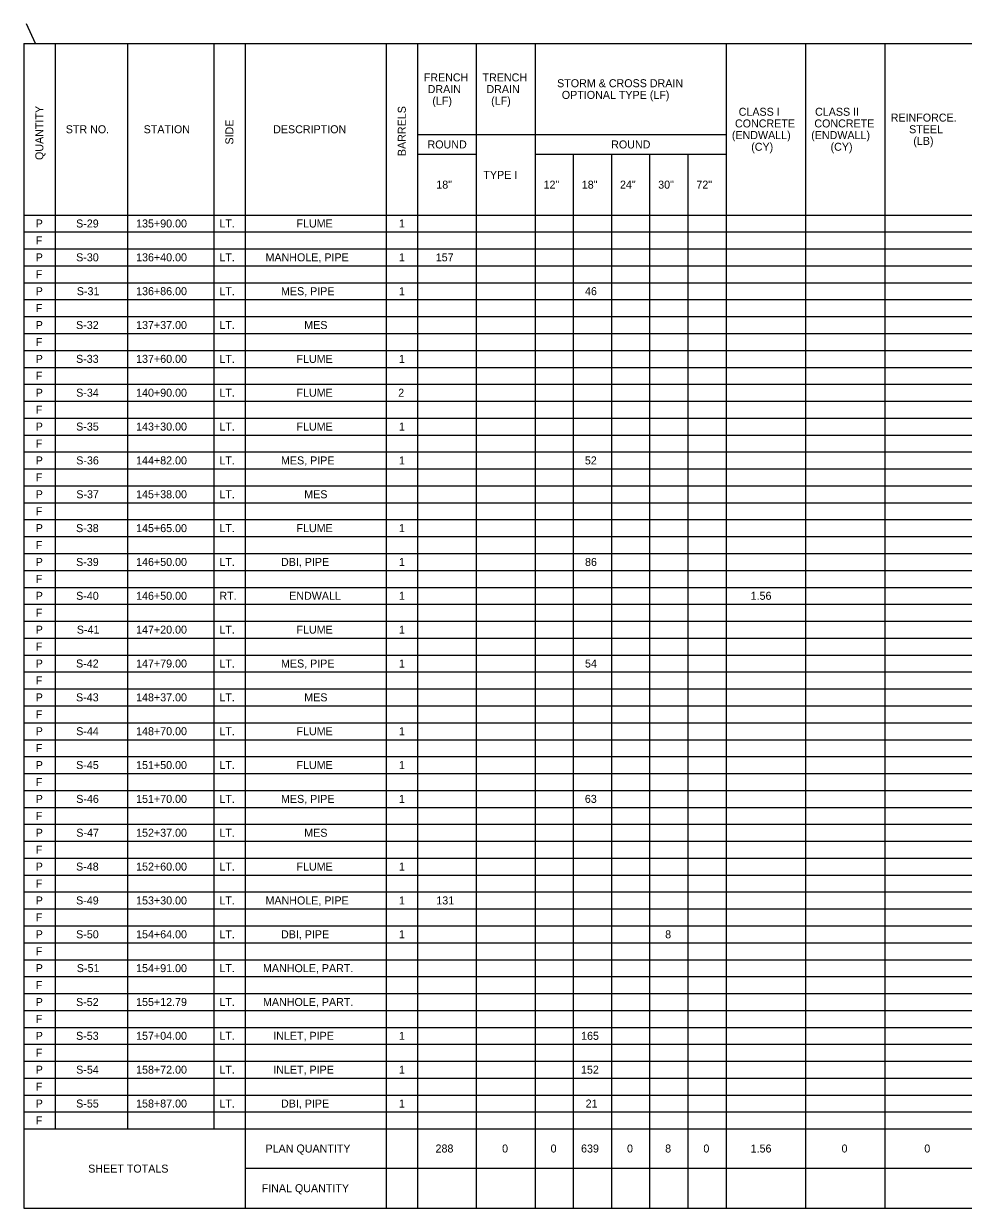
# Model space of a CAD drawing. Extents: x 0 to 765, y -1227 to 479.
# Drawn here: x 0.3 to 360, y -569 to -115.7 of the extents above; entities that cross this region are included whole.
import ezdxf

# ---------------------------------------------------------------- set-up
doc = ezdxf.new("R2010")
doc.units = 0
for name, color, linetype in [('Miscellaneous0', 7, 'Continuous'), ('PlotBorder_dp', 7, 'Continuous'), ('SheetLines_dp', 7, 'Continuous'), ('TextMinor', 7, 'Continuous'), ('TextShtNo', 7, 'Continuous')]:
    doc.layers.add(name, color=color, linetype=linetype)

msp = doc.modelspace()

# ---------------------------------------------------------------- linework, layer by layer
at = {"layer": 'PlotBorder_dp'}
for p, q in [((12.29, -123.31), (12.29, -538.58)), ((12.29, -123.31), (12.29, -538.58)), ((40.04, -123.31), (40.04, -538.58)), ((40.04, -123.31), (40.04, -538.58)), ((73.04, -123.31), (73.04, -538.58)), ((85.04, -123.31), (85.04, -568.96)), ((139.04, -123.31), (139.04, -568.96)), ((151.04, -123.31), (151.04, -568.96)), ((151.04, -123.31), (151.04, -568.96)), ((173.54, -123.31), (173.54, -568.96)), ((173.54, -123.31), (173.54, -568.96)), ((196.04, -123.31), (196.04, -568.96)), ((196.04, -123.31), (196.04, -568.96)), ((269.16, -123.31), (269.16, -568.96)), ((269.16, -123.31), (269.16, -568.96)), ((299.54, -123.31), (299.54, -188.93)), ((299.54, -123.31), (299.54, -568.96)), ((329.91, -123.31), (329.91, -188.93)), ((329.91, -123.31), (329.91, -568.96)), ((151.04, -158.18), (269.16, -158.18)), ((151.04, -165.68), (173.54, -165.68)), ((151.04, -165.68), (173.54, -165.68)), ((196.04, -165.68), (269.16, -165.68)), ((196.04, -165.68), (269.16, -165.68)), ((210.66, -165.68), (210.66, -568.96)), ((210.66, -165.68), (210.66, -568.96)), ((225.29, -165.68), (225.29, -568.96)), ((225.29, -165.68), (225.29, -568.96)), ((239.91, -165.68), (239.91, -568.96)), ((239.91, -165.68), (239.91, -568.96)), ((254.54, -165.68), (254.54, -553.58)), ((254.54, -165.68), (254.54, -568.96)), ((73.04, -188.93), (73.04, -538.58)), ((85.04, -188.93), (85.04, -568.96)), ((139.04, -188.93), (139.04, -568.96)), ((299.54, -422.03), (299.54, -568.96)), ((329.91, -422.03), (329.91, -568.96)), ((0.29, -538.58), (764.54, -538.58)), ((85.04, -553.58), (764.54, -553.58)), ((85.04, -553.58), (764.54, -553.58))]:
    msp.add_line(p, q, dxfattribs=at)
at = {"layer": 'SheetLines_dp'}
for p, q in [((0.29, -123.31), (764.54, -123.31)), ((0.29, -123.31), (0.29, -568.96)), ((0.29, -188.93), (764.54, -188.93)), ((0.29, -188.93), (12.29, -188.93)), ((40.04, -188.93), (764.54, -188.93)), ((0.29, -568.96), (764.54, -568.96))]:
    msp.add_line(p, q, dxfattribs=at)
at = {"layer": 'TextMinor'}
for p, q in [((12.29, -188.93), (40.04, -188.93)), ((0.29, -195.41), (151.04, -195.41)), ((0.29, -195.41), (764.54, -195.41)), ((173.54, -195.41), (406.79, -195.41)), ((0.29, -201.88), (764.54, -201.88)), ((0.29, -201.88), (764.54, -201.88)), ((0.29, -208.36), (764.54, -208.36)), ((0.29, -208.36), (764.54, -208.36)), ((0.29, -214.83), (764.54, -214.83)), ((0.29, -214.83), (764.54, -214.83)), ((0.29, -221.31), (764.54, -221.31)), ((0.29, -221.31), (764.54, -221.31)), ((0.29, -227.78), (764.54, -227.78)), ((0.29, -227.78), (764.54, -227.78)), ((0.29, -234.26), (764.54, -234.26)), ((0.29, -234.26), (764.54, -234.26)), ((0.29, -240.73), (764.54, -240.73)), ((0.29, -240.73), (764.54, -240.73)), ((0.29, -247.21), (764.54, -247.21)), ((0.29, -247.21), (764.54, -247.21)), ((0.29, -253.68), (764.54, -253.68)), ((0.29, -253.68), (764.54, -253.68)), ((0.29, -260.16), (764.54, -260.16)), ((0.29, -260.16), (764.54, -260.16)), ((0.29, -266.63), (764.54, -266.63)), ((0.29, -266.63), (764.54, -266.63)), ((0.29, -273.11), (764.54, -273.11)), ((0.29, -273.11), (764.54, -273.11)), ((0.29, -279.58), (764.54, -279.58)), ((0.29, -279.58), (764.54, -279.58)), ((0.29, -286.06), (764.54, -286.06)), ((0.29, -286.06), (764.54, -286.06)), ((0.29, -292.53), (764.54, -292.53)), ((0.29, -292.53), (764.54, -292.53)), ((0.29, -299.01), (764.54, -299.01)), ((0.29, -299.01), (764.54, -299.01)), ((0.29, -305.48), (764.54, -305.48)), ((0.29, -305.48), (764.54, -305.48)), ((0.29, -311.96), (764.54, -311.96)), ((0.29, -311.96), (764.54, -311.96)), ((0.29, -318.43), (764.54, -318.43)), ((0.29, -318.43), (764.54, -318.43)), ((0.29, -324.91), (764.54, -324.91)), ((0.29, -324.91), (764.54, -324.91)), ((0.29, -331.38), (764.54, -331.38)), ((0.29, -331.38), (764.54, -331.38)), ((0.29, -337.86), (764.54, -337.86)), ((0.29, -337.86), (764.54, -337.86)), ((0.29, -344.33), (764.54, -344.33)), ((0.29, -344.33), (764.54, -344.33)), ((0.29, -350.81), (764.54, -350.81)), ((0.29, -350.81), (764.54, -350.81)), ((0.29, -357.28), (764.54, -357.28)), ((0.29, -357.28), (764.54, -357.28)), ((0.29, -363.76), (764.54, -363.76)), ((0.29, -363.76), (764.54, -363.76)), ((0.29, -370.23), (764.54, -370.23)), ((0.29, -370.23), (764.54, -370.23)), ((0.29, -376.71), (764.54, -376.71)), ((0.29, -376.71), (764.54, -376.71)), ((0.29, -383.18), (764.54, -383.18)), ((0.29, -383.18), (764.54, -383.18)), ((0.29, -389.66), (764.54, -389.66)), ((0.29, -389.66), (764.54, -389.66)), ((0.29, -396.13), (764.54, -396.13)), ((0.29, -396.13), (764.54, -396.13)), ((0.29, -402.61), (764.54, -402.61)), ((0.29, -402.61), (764.54, -402.61)), ((0.29, -409.08), (764.54, -409.08)), ((0.29, -409.08), (764.54, -409.08)), ((0.29, -415.56), (764.54, -415.56)), ((0.29, -415.56), (764.54, -415.56)), ((0.29, -422.03), (764.54, -422.03)), ((0.29, -422.03), (764.54, -422.03)), ((0.29, -428.51), (764.54, -428.51)), ((0.29, -428.51), (764.54, -428.51)), ((0.29, -434.98), (764.54, -434.98)), ((0.29, -434.98), (764.54, -434.98)), ((0.29, -441.46), (764.54, -441.46)), ((0.29, -441.46), (764.54, -441.46)), ((0.29, -447.93), (764.54, -447.93)), ((0.29, -447.93), (764.54, -447.93)), ((0.29, -454.41), (764.54, -454.41)), ((0.29, -454.41), (764.54, -454.41)), ((0.29, -460.88), (764.54, -460.88)), ((0.29, -460.88), (764.54, -460.88)), ((0.29, -467.36), (764.54, -467.36)), ((0.29, -467.36), (764.54, -467.36)), ((0.29, -473.83), (764.54, -473.83)), ((0.29, -473.83), (764.54, -473.83)), ((0.29, -480.31), (764.54, -480.31)), ((0.29, -480.31), (764.54, -480.31)), ((0.29, -486.78), (764.54, -486.78)), ((0.29, -486.78), (764.54, -486.78)), ((0.29, -493.26), (764.54, -493.26)), ((0.29, -493.26), (764.54, -493.26)), ((0.29, -499.73), (764.54, -499.73)), ((0.29, -499.73), (764.54, -499.73)), ((0.29, -506.21), (764.54, -506.21)), ((0.29, -506.21), (764.54, -506.21)), ((0.29, -512.68), (764.54, -512.68)), ((0.29, -512.68), (764.54, -512.68)), ((0.29, -519.16), (764.54, -519.16)), ((0.29, -519.16), (764.54, -519.16)), ((0.29, -525.63), (764.54, -525.63)), ((0.29, -525.63), (764.54, -525.63)), ((0.29, -532.11), (764.54, -532.11)), ((0.29, -532.11), (764.54, -532.11)), ((0.29, -538.58), (764.54, -538.58))]:
    msp.add_line(p, q, dxfattribs=at)
at = {"layer": 'TextShtNo'}
msp.add_line((4.8, -123.31), (1.37, -115.73), dxfattribs=at)

# ---------------------------------------------------------------- texts
at = {"layer": 'Miscellaneous0'}
for s, height, p in [('FRENCH', 3.062, (153.45, -137.81)), ('TRENCH', 3.062, (175.95, -137.81)), ('DRAIN', 3.062, (154.94, -142.28)), ('DRAIN', 3.062, (177.44, -142.28)), ('STORM & CROSS DRAIN', 3.0625, (204.5, -140.04)), ('(LF)', 3.062, (156.74, -146.74)), ('(LF)', 3.062, (179.24, -146.74)), ('OPTIONAL TYPE (LF)', 3.0625, (206.3, -144.51)), (' CLASS I', 3.062, (272.87, -150.96)), ('CLASS II', 3.062, (303.25, -150.96)), ('CONCRETE', 3.062, (272.59, -155.42)), ('CONCRETE', 3.062, (302.97, -155.42)), ('REINFORCE.', 3.062, (332.2, -153.19)), ('STR NO.', 3.062, (16.4, -157.65)), ('STATION', 3.062, (46.22, -157.65)), ('DESCRIPTION', 3.0625, (95.79, -157.65)), ('(ENDWALL)', 3.062, (271.39, -159.88)), ('(ENDWALL)', 3.062, (301.77, -159.88)), ('STEEL', 3.062, (339.25, -157.65)), ('ROUND', 3.062, (154.89, -163.46)), ('ROUND', 3.062, (225.2, -163.46)), ('(CY)', 3.062, (278.8, -164.35)), ('(CY)', 3.062, (309.18, -164.35)), ('(LB)', 3.062, (340.86, -162.11)), ('TYPE I', 3.062, (176.27, -175.09)), ('18"', 3.062, (158.25, -178.84)), ('12"', 3.062, (199.31, -178.84)), ('18"', 3.062, (213.94, -178.84)), ('24"', 3.062, (228.56, -178.84)), ('30"', 3.062, (243.19, -178.84)), ('72"', 3.062, (257.81, -178.84)), ('P', 3.06, (4.9, -193.7)), ('S-29', 3.062, (20.36, -193.7)), ('135+90.00', 3.062, (43.33, -193.7)), ('LT.', 3.062, (75.2, -193.7)), ('FLUME', 3.062, (104.73, -193.7)), ('1', 3.06, (143.96, -193.7)), ('F', 3.06, (4.95, -200.18)), ('P', 3.06, (4.9, -206.65)), ('S-30', 3.062, (20.37, -206.65)), ('136+40.00', 3.062, (43.33, -206.65)), ('LT.', 3.062, (75.2, -206.65)), ('MANHOLE, PIPE', 3.0625, (92.87, -206.65)), ('1', 3.06, (143.96, -206.65)), ('157', 3.062, (158.04, -206.65)), ('F', 3.06, (4.95, -213.13)), ('P', 3.06, (4.9, -219.6)), ('S-31', 3.062, (20.64, -219.6)), ('136+86.00', 3.062, (43.33, -219.6)), ('LT.', 3.062, (75.2, -219.6)), ('MES, PIPE', 3.062, (98.8, -219.6)), ('1', 3.06, (143.96, -219.6)), ('46', 3.062, (215.18, -219.6)), ('F', 3.06, (4.95, -226.08)), ('P', 3.06, (4.9, -232.55)), ('S-32', 3.062, (20.34, -232.55)), ('137+37.00', 3.062, (43.33, -232.55)), ('LT.', 3.062, (75.2, -232.55)), ('MES', 3.062, (107.7, -232.55)), ('F', 3.06, (4.95, -239.03)), ('P', 3.06, (4.9, -245.5)), ('S-33', 3.062, (20.34, -245.5)), ('137+60.00', 3.062, (43.33, -245.5)), ('LT.', 3.062, (75.2, -245.5)), ('FLUME', 3.062, (104.73, -245.5)), ('1', 3.06, (143.96, -245.5)), ('F', 3.06, (4.95, -251.98)), ('P', 3.06, (4.9, -258.45)), ('S-34', 3.062, (20.4, -258.45)), ('140+90.00', 3.062, (43.33, -258.45)), ('LT.', 3.062, (75.2, -258.45)), ('FLUME', 3.062, (104.73, -258.45)), ('2', 3.06, (143.67, -258.45)), ('F', 3.06, (4.95, -264.93)), ('P', 3.06, (4.9, -271.4)), ('S-35', 3.062, (20.38, -271.4)), ('143+30.00', 3.062, (43.33, -271.4)), ('LT.', 3.062, (75.2, -271.4)), ('FLUME', 3.062, (104.73, -271.4)), ('1', 3.06, (143.96, -271.4)), ('F', 3.06, (4.95, -277.88)), ('P', 3.06, (4.9, -284.35)), ('S-36', 3.062, (20.41, -284.35)), ('144+82.00', 3.062, (43.33, -284.35)), ('LT.', 3.062, (75.2, -284.35)), ('MES, PIPE', 3.062, (98.8, -284.35)), ('1', 3.06, (143.96, -284.35)), ('52', 3.062, (215.12, -284.35)), ('F', 3.06, (4.95, -290.83)), ('P', 3.06, (4.9, -297.3)), ('S-37', 3.062, (20.43, -297.3)), ('145+38.00', 3.062, (43.33, -297.3)), ('LT.', 3.062, (75.2, -297.3)), ('MES', 3.062, (107.7, -297.3)), ('F', 3.06, (4.95, -303.78)), ('P', 3.06, (4.9, -310.25)), ('S-38', 3.062, (20.35, -310.25)), ('145+65.00', 3.062, (43.33, -310.25)), ('LT.', 3.062, (75.2, -310.25)), ('FLUME', 3.062, (104.73, -310.25)), ('1', 3.06, (143.96, -310.25)), ('F', 3.06, (4.95, -316.73)), ('P', 3.06, (4.9, -323.2)), ('S-39', 3.062, (20.36, -323.2)), ('146+50.00', 3.062, (43.33, -323.2)), ('LT.', 3.062, (75.2, -323.2)), ('DBI, PIPE', 3.062, (98.8, -323.2)), ('1', 3.06, (143.96, -323.2)), ('86', 3.062, (215.18, -323.2)), ('F', 3.06, (4.95, -329.68)), ('P', 3.06, (4.9, -336.15)), ('S-40', 3.062, (20.37, -336.15)), ('146+50.00', 3.062, (43.33, -336.15)), ('RT.', 3.062, (75.2, -336.15)), ('ENDWALL', 3.062, (101.92, -336.15)), ('1', 3.06, (143.96, -336.15)), ('1.56', 3.062, (278.59, -336.15)), ('F', 3.06, (4.95, -342.63)), ('P', 3.06, (4.9, -349.1)), ('S-41', 3.062, (20.64, -349.1)), ('147+20.00', 3.062, (43.33, -349.1)), ('LT.', 3.062, (75.2, -349.1)), ('FLUME', 3.062, (104.73, -349.1)), ('1', 3.06, (143.96, -349.1)), ('F', 3.06, (4.95, -355.58)), ('P', 3.06, (4.9, -362.05)), ('S-42', 3.062, (20.34, -362.05)), ('147+79.00', 3.062, (43.33, -362.05)), ('LT.', 3.062, (75.2, -362.05)), ('MES, PIPE', 3.062, (98.8, -362.05)), ('1', 3.06, (143.96, -362.05)), ('54', 3.062, (215.18, -362.05)), ('F', 3.06, (4.95, -368.53)), ('P', 3.06, (4.9, -375)), ('S-43', 3.062, (20.34, -375)), ('148+37.00', 3.062, (43.33, -375)), ('LT.', 3.062, (75.2, -375)), ('MES', 3.062, (107.7, -375)), ('F', 3.06, (4.95, -381.48)), ('P', 3.06, (4.9, -387.95)), ('S-44', 3.062, (20.4, -387.95)), ('148+70.00', 3.062, (43.33, -387.95)), ('LT.', 3.062, (75.2, -387.95)), ('FLUME', 3.062, (104.73, -387.95)), ('1', 3.06, (143.96, -387.95)), ('F', 3.06, (4.95, -394.43)), ('P', 3.06, (4.9, -400.9)), ('S-45', 3.062, (20.38, -400.9)), ('151+50.00', 3.062, (43.33, -400.9)), ('LT.', 3.062, (75.2, -400.9)), ('FLUME', 3.062, (104.73, -400.9)), ('1', 3.06, (143.96, -400.9)), ('F', 3.06, (4.95, -407.38)), ('P', 3.06, (4.9, -413.85)), ('S-46', 3.062, (20.41, -413.85)), ('151+70.00', 3.062, (43.33, -413.85)), ('LT.', 3.062, (75.2, -413.85)), ('MES, PIPE', 3.062, (98.8, -413.85)), ('1', 3.06, (143.96, -413.85)), ('63', 3.062, (215.12, -413.85)), ('F', 3.06, (4.95, -420.33)), ('P', 3.06, (4.9, -426.8)), ('S-47', 3.062, (20.43, -426.8)), ('152+37.00', 3.062, (43.33, -426.8)), ('LT.', 3.062, (75.2, -426.8)), ('MES', 3.062, (107.7, -426.8)), ('F', 3.06, (4.95, -433.28)), ('P', 3.06, (4.9, -439.75)), ('S-48', 3.062, (20.35, -439.75)), ('152+60.00', 3.062, (43.33, -439.75)), ('LT.', 3.062, (75.2, -439.75)), ('FLUME', 3.062, (104.73, -439.75)), ('1', 3.06, (143.96, -439.75)), ('F', 3.06, (4.95, -446.23)), ('P', 3.06, (4.9, -452.7)), ('S-49', 3.062, (20.36, -452.7)), ('153+30.00', 3.062, (43.33, -452.7)), ('LT.', 3.062, (75.2, -452.7)), ('MANHOLE, PIPE', 3.0625, (92.87, -452.7)), ('1', 3.06, (143.96, -452.7)), ('131', 3.062, (158.25, -452.7)), ('F', 3.06, (4.95, -459.18)), ('P', 3.06, (4.9, -465.65)), ('S-50', 3.062, (20.37, -465.65)), ('154+64.00', 3.062, (43.33, -465.65)), ('LT.', 3.062, (75.2, -465.65)), ('DBI, PIPE', 3.062, (98.8, -465.65)), ('1', 3.06, (143.96, -465.65)), ('8', 3.06, (245.86, -465.65)), ('F', 3.06, (4.95, -472.13)), ('P', 3.06, (4.9, -478.6)), ('S-51', 3.062, (20.64, -478.6)), ('154+91.00', 3.062, (43.33, -478.6)), ('LT.', 3.062, (75.2, -478.6)), ('MANHOLE, PART.', 3.0625, (91.9, -478.6)), ('F', 3.06, (4.95, -485.08)), ('P', 3.06, (4.9, -491.55)), ('S-52', 3.062, (20.34, -491.55)), ('155+12.79', 3.062, (43.33, -491.55)), ('LT.', 3.062, (75.2, -491.55)), ('MANHOLE, PART.', 3.0625, (91.9, -491.55)), ('F', 3.06, (4.95, -498.03)), ('P', 3.06, (4.9, -504.5)), ('S-53', 3.062, (20.34, -504.5)), ('157+04.00', 3.062, (43.33, -504.5)), ('LT.', 3.062, (75.2, -504.5)), ('INLET, PIPE', 3.0625, (95.83, -504.5)), ('1', 3.06, (143.96, -504.5)), ('165', 3.062, (213.68, -504.5)), ('F', 3.06, (4.95, -510.98)), ('P', 3.06, (4.9, -517.45)), ('S-54', 3.062, (20.4, -517.45)), ('158+72.00', 3.062, (43.33, -517.45)), ('LT.', 3.062, (75.2, -517.45)), ('INLET, PIPE', 3.0625, (95.83, -517.45)), ('1', 3.06, (143.96, -517.45)), ('152', 3.062, (213.64, -517.45)), ('F', 3.06, (4.95, -523.93)), ('P', 3.06, (4.9, -530.4)), ('S-55', 3.062, (20.38, -530.4)), ('158+87.00', 3.062, (43.33, -530.4)), ('LT.', 3.062, (75.2, -530.4)), ('DBI, PIPE', 3.062, (98.8, -530.4)), ('1', 3.06, (143.96, -530.4)), ('21', 3.062, (215.42, -530.4)), ('F', 3.06, (4.95, -536.88)), ('PLAN QUANTITY', 3.0625, (92.87, -547.61)), ('288', 3.062, (157.96, -547.61)), ('0', 3.06, (183.44, -547.61)), ('0', 3.06, (202, -547.61)), ('639', 3.062, (213.66, -547.61)), ('0', 3.06, (231.25, -547.61)), ('8', 3.06, (245.86, -547.61)), ('0', 3.06, (260.5, -547.61)), ('1.56', 3.062, (278.59, -547.61)), ('0', 3.06, (313.38, -547.61)), ('0', 3.06, (345.07, -547.61)), ('SHEET TOTALS', 3.0625, (24.98, -555.3)), ('FINAL QUANTITY', 3.0625, (91.39, -562.8))]:
    msp.add_text(s, height=height, dxfattribs=at).set_placement(p)
for s, p in [('QUANTITY', (7.82, -167.88)), ('BARRELS', (146.57, -166.39)), ('SIDE', (80.57, -161.95))]:
    msp.add_text(s, height=3.062, rotation=90, dxfattribs=at).set_placement(p)

doc.saveas('drawing.dxf')
